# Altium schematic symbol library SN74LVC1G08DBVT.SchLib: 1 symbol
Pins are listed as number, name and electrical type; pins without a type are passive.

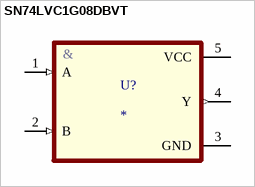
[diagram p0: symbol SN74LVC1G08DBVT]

## SN74LVC1G08DBVT
designator U?
AND IC 1 chanal SOT-23-5; MF: Texas Instruments; MP: SN74LVC1G08DBV
footprint SOT23-5
pins: 1 A (in), 2 B (in), 3 GND, 4 Y (out), 5 VCC (power)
